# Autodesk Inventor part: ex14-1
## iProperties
Author: J. DESIGNER
Revision Number: A
Shininess: 88.0
Angle Display Precision: 2
Document Length Units: 11272
Document Angle Units: 11286
Document Time Units: 11279
Document Mass Units: 11290
Document Length Units Precision: 3
Document Angle Units Precision: 2
Compacted: False
PropertySet Name: _Private Model Information
Created: 2001-10
Part Number: ex14-1
Description: FRAME, SCOOTER
Document SubType Name: Modeling
Designer: J. DESIGNER
Control State: 0
Master: False
Checked Out: False
PropertySet Name: Design Tracking Control
Density: 0.0
Volumn: 0.0
Area: 0.0
PropertySet Name: Model Information
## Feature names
1. Sweep1
2. Sweep2
3. Extrusion2
4. Extrusion3
5. Fillet1
6. Sweep3
7. Mirror1
8. Extrusion4
9. Extrusion5
10. Extrusion6
11. Loft1
12. Mirror2
13. Extrusion7
14. Hole1
